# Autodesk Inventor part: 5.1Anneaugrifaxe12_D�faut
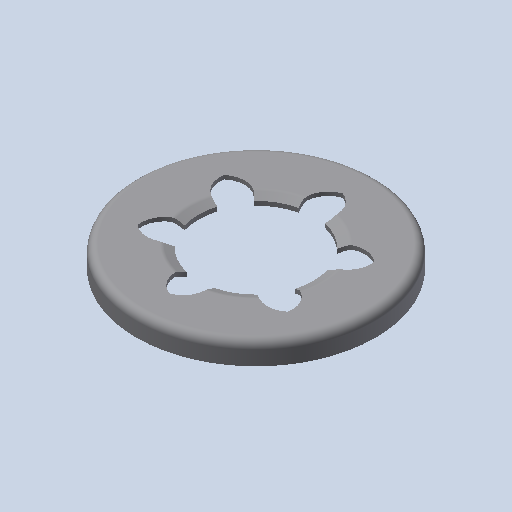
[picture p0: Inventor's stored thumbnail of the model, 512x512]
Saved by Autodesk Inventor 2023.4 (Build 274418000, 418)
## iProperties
Created: 2011-01
Part Number: 5.1Anneaugrifaxe12_D�faut
Document SubType Name: Modeling
Designer: eric
Density: 1 g/cm^3
Mass: 0.183487 g
Surface Area: 9.77041 cm^2
Volume: 0.183487 cm^3
Material: Générique
Appearance: Par défaut
Author: eric
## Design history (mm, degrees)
feature "Base1"
node "Corps solides"
node "Corps surfaciques"
node "Solide1"
